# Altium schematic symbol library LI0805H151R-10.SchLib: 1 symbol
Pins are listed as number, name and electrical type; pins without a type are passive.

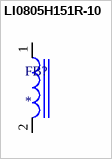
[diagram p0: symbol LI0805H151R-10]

## LI0805H151R-10
designator FB?
150 Ohms @ 100MHz 1 Power, Signal Line Ferrite Bead 0805 (2012 Metric) 800mA 150mOhm; MP: LI0805H151R-10; MF: Laird-Signal Integrity
footprint LI0805H151R-10
pins: 1, 2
